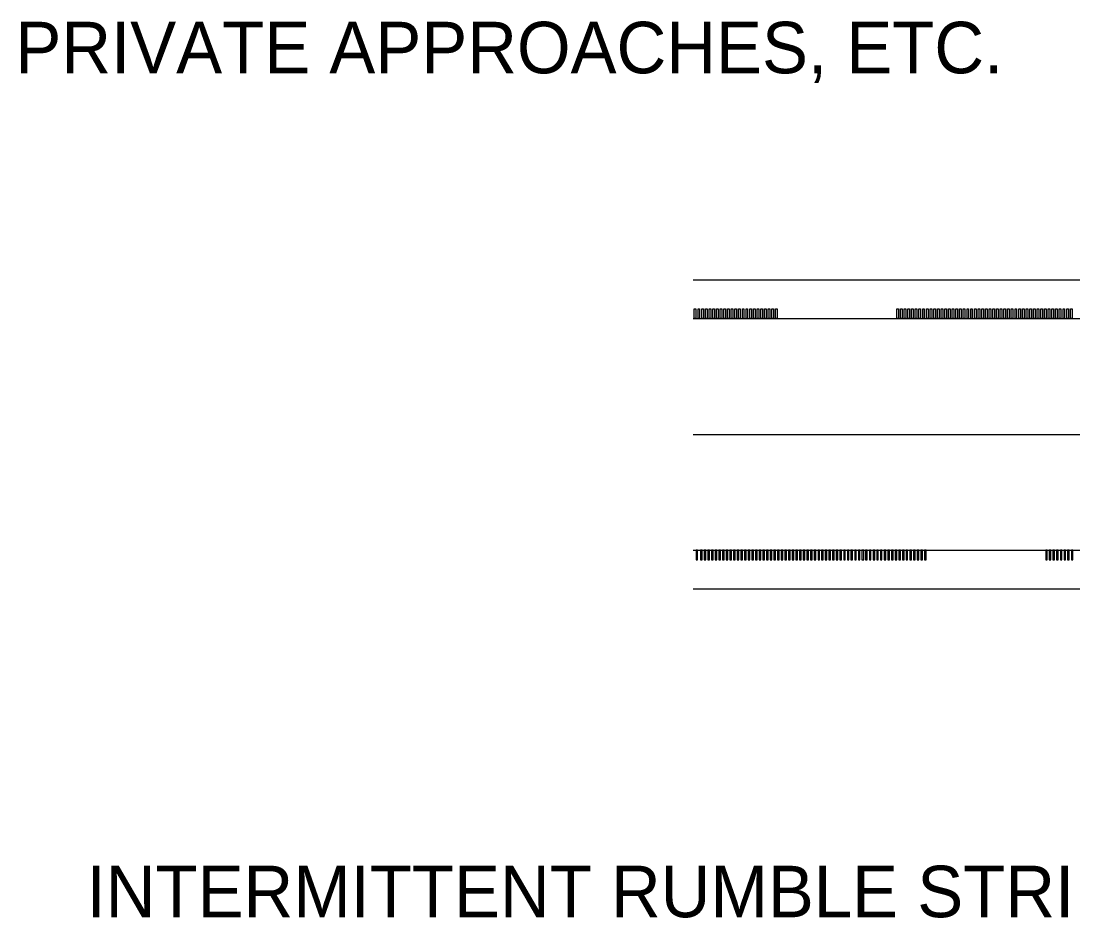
# Model space of a CAD drawing. Extents: x 49991.4 to 50021, y 49987.6 to 50011.4.
# Drawn here: x 50004.547 to 50005.772, y 49993.776 to 49994.821 of the extents above; entities that cross this region are included whole.
import ezdxf

# ---------------------------------------------------------------- set-up
doc = ezdxf.new("R2010")
doc.units = 0
doc.layers.add('Level 1', color=7, linetype='Continuous')
doc.layers.add('Level 2', color=7, linetype='Continuous')

msp = doc.modelspace()

# ---------------------------------------------------------------- linework, layer by layer
at = {"layer": 'Level 1'}
for p, q in [((50005.3297, 49994.5195), (50011.7149, 49994.5195)), ((50005.3297, 49994.4745), (50011.7149, 49994.4745)), ((50005.3297, 49994.3395), (50011.7149, 49994.3395)), ((50005.3299, 49994.2045), (50011.7149, 49994.2045)), ((50005.3299, 49994.1595), (50006.9691, 49994.1595))]:
    msp.add_line(p, q, dxfattribs=at)
for points in [[(50005.3331, 49994.4745), (50005.3312, 49994.4745), (50005.3312, 49994.4857), (50005.3331, 49994.4857)], [(50005.3374, 49994.4745), (50005.3355, 49994.4745), (50005.3355, 49994.4857), (50005.3374, 49994.4857)], [(50005.3417, 49994.4745), (50005.3398, 49994.4745), (50005.3398, 49994.4857), (50005.3417, 49994.4857)], [(50005.346, 49994.4745), (50005.3441, 49994.4745), (50005.3441, 49994.4857), (50005.346, 49994.4857)], [(50005.3503, 49994.4745), (50005.3484, 49994.4745), (50005.3484, 49994.4857), (50005.3503, 49994.4857)], [(50005.3546, 49994.4745), (50005.3527, 49994.4745), (50005.3527, 49994.4857), (50005.3546, 49994.4857)], [(50005.3589, 49994.4745), (50005.357, 49994.4745), (50005.357, 49994.4857), (50005.3589, 49994.4857)], [(50005.3632, 49994.4745), (50005.3613, 49994.4745), (50005.3613, 49994.4857), (50005.3632, 49994.4857)], [(50005.3675, 49994.4745), (50005.3656, 49994.4745), (50005.3656, 49994.4857), (50005.3675, 49994.4857)], [(50005.3718, 49994.4745), (50005.3699, 49994.4745), (50005.3699, 49994.4857), (50005.3718, 49994.4857)], [(50005.3761, 49994.4745), (50005.3742, 49994.4745), (50005.3742, 49994.4857), (50005.3761, 49994.4857)], [(50005.3804, 49994.4745), (50005.3785, 49994.4745), (50005.3785, 49994.4857), (50005.3804, 49994.4857)], [(50005.3847, 49994.4745), (50005.3828, 49994.4745), (50005.3828, 49994.4857), (50005.3847, 49994.4857)], [(50005.389, 49994.4745), (50005.3871, 49994.4745), (50005.3871, 49994.4857), (50005.389, 49994.4857)], [(50005.3933, 49994.4745), (50005.3914, 49994.4745), (50005.3914, 49994.4857), (50005.3933, 49994.4857)], [(50005.3976, 49994.4745), (50005.3957, 49994.4745), (50005.3957, 49994.4857), (50005.3976, 49994.4857)], [(50005.4019, 49994.4745), (50005.4, 49994.4745), (50005.4, 49994.4857), (50005.4019, 49994.4857)], [(50005.4062, 49994.4745), (50005.4043, 49994.4745), (50005.4043, 49994.4857), (50005.4062, 49994.4857)], [(50005.4105, 49994.4745), (50005.4086, 49994.4745), (50005.4086, 49994.4857), (50005.4105, 49994.4857)], [(50005.4148, 49994.4745), (50005.4129, 49994.4745), (50005.4129, 49994.4857), (50005.4148, 49994.4857)], [(50005.4191, 49994.4745), (50005.4172, 49994.4745), (50005.4172, 49994.4857), (50005.4191, 49994.4857)], [(50005.4234, 49994.4745), (50005.4215, 49994.4745), (50005.4215, 49994.4857), (50005.4234, 49994.4857)], [(50005.4277, 49994.4745), (50005.4258, 49994.4745), (50005.4258, 49994.4857), (50005.4277, 49994.4857)], [(50005.5689, 49994.4745), (50005.567, 49994.4745), (50005.567, 49994.4857), (50005.5689, 49994.4857)], [(50005.5732, 49994.4745), (50005.5713, 49994.4745), (50005.5713, 49994.4857), (50005.5732, 49994.4857)], [(50005.5775, 49994.4745), (50005.5756, 49994.4745), (50005.5756, 49994.4857), (50005.5775, 49994.4857)], [(50005.5818, 49994.4745), (50005.5799, 49994.4745), (50005.5799, 49994.4857), (50005.5818, 49994.4857)], [(50005.5861, 49994.4745), (50005.5842, 49994.4745), (50005.5842, 49994.4857), (50005.5861, 49994.4857)], [(50005.5904, 49994.4745), (50005.5885, 49994.4745), (50005.5885, 49994.4857), (50005.5904, 49994.4857)], [(50005.5947, 49994.4745), (50005.5928, 49994.4745), (50005.5928, 49994.4857), (50005.5947, 49994.4857)], [(50005.599, 49994.4745), (50005.5971, 49994.4745), (50005.5971, 49994.4857), (50005.599, 49994.4857)], [(50005.6033, 49994.4745), (50005.6014, 49994.4745), (50005.6014, 49994.4857), (50005.6033, 49994.4857)], [(50005.6076, 49994.4745), (50005.6057, 49994.4745), (50005.6057, 49994.4857), (50005.6076, 49994.4857)], [(50005.6119, 49994.4745), (50005.61, 49994.4745), (50005.61, 49994.4857), (50005.6119, 49994.4857)], [(50005.6162, 49994.4745), (50005.6143, 49994.4745), (50005.6143, 49994.4857), (50005.6162, 49994.4857)], [(50005.6205, 49994.4745), (50005.6186, 49994.4745), (50005.6186, 49994.4857), (50005.6205, 49994.4857)], [(50005.6248, 49994.4745), (50005.6229, 49994.4745), (50005.6229, 49994.4857), (50005.6248, 49994.4857)], [(50005.6291, 49994.4745), (50005.6272, 49994.4745), (50005.6272, 49994.4857), (50005.6291, 49994.4857)], [(50005.6334, 49994.4745), (50005.6315, 49994.4745), (50005.6315, 49994.4857), (50005.6334, 49994.4857)], [(50005.6377, 49994.4745), (50005.6358, 49994.4745), (50005.6358, 49994.4857), (50005.6377, 49994.4857)], [(50005.642, 49994.4745), (50005.6401, 49994.4745), (50005.6401, 49994.4857), (50005.642, 49994.4857)], [(50005.6463, 49994.4745), (50005.6444, 49994.4745), (50005.6444, 49994.4857), (50005.6463, 49994.4857)], [(50005.6506, 49994.4745), (50005.6487, 49994.4745), (50005.6487, 49994.4857), (50005.6506, 49994.4857)], [(50005.6549, 49994.4745), (50005.653, 49994.4745), (50005.653, 49994.4857), (50005.6549, 49994.4857)], [(50005.6592, 49994.4745), (50005.6573, 49994.4745), (50005.6573, 49994.4857), (50005.6592, 49994.4857)], [(50005.6635, 49994.4745), (50005.6616, 49994.4745), (50005.6616, 49994.4857), (50005.6635, 49994.4857)], [(50005.6678, 49994.4745), (50005.6659, 49994.4745), (50005.6659, 49994.4857), (50005.6678, 49994.4857)], [(50005.6721, 49994.4745), (50005.6702, 49994.4745), (50005.6702, 49994.4857), (50005.6721, 49994.4857)], [(50005.6764, 49994.4745), (50005.6745, 49994.4745), (50005.6745, 49994.4857), (50005.6764, 49994.4857)], [(50005.6807, 49994.4745), (50005.6788, 49994.4745), (50005.6788, 49994.4857), (50005.6807, 49994.4857)], [(50005.685, 49994.4745), (50005.6831, 49994.4745), (50005.6831, 49994.4857), (50005.685, 49994.4857)], [(50005.6893, 49994.4745), (50005.6874, 49994.4745), (50005.6874, 49994.4857), (50005.6893, 49994.4857)], [(50005.6936, 49994.4745), (50005.6917, 49994.4745), (50005.6917, 49994.4857), (50005.6936, 49994.4857)], [(50005.6979, 49994.4745), (50005.696, 49994.4745), (50005.696, 49994.4857), (50005.6979, 49994.4857)], [(50005.7022, 49994.4745), (50005.7003, 49994.4745), (50005.7003, 49994.4857), (50005.7022, 49994.4857)], [(50005.7065, 49994.4745), (50005.7046, 49994.4745), (50005.7046, 49994.4857), (50005.7065, 49994.4857)], [(50005.7108, 49994.4745), (50005.7089, 49994.4745), (50005.7089, 49994.4857), (50005.7108, 49994.4857)], [(50005.7151, 49994.4745), (50005.7132, 49994.4745), (50005.7132, 49994.4857), (50005.7151, 49994.4857)], [(50005.7194, 49994.4745), (50005.7175, 49994.4745), (50005.7175, 49994.4857), (50005.7194, 49994.4857)], [(50005.7237, 49994.4745), (50005.7218, 49994.4745), (50005.7218, 49994.4857), (50005.7237, 49994.4857)], [(50005.728, 49994.4745), (50005.7261, 49994.4745), (50005.7261, 49994.4857), (50005.728, 49994.4857)], [(50005.7323, 49994.4745), (50005.7304, 49994.4745), (50005.7304, 49994.4857), (50005.7323, 49994.4857)], [(50005.7366, 49994.4745), (50005.7347, 49994.4745), (50005.7347, 49994.4857), (50005.7366, 49994.4857)], [(50005.7409, 49994.4745), (50005.739, 49994.4745), (50005.739, 49994.4857), (50005.7409, 49994.4857)], [(50005.7452, 49994.4745), (50005.7433, 49994.4745), (50005.7433, 49994.4857), (50005.7452, 49994.4857)], [(50005.7495, 49994.4745), (50005.7476, 49994.4745), (50005.7476, 49994.4857), (50005.7495, 49994.4857)], [(50005.7538, 49994.4745), (50005.7519, 49994.4745), (50005.7519, 49994.4857), (50005.7538, 49994.4857)], [(50005.7581, 49994.4745), (50005.7562, 49994.4745), (50005.7562, 49994.4857), (50005.7581, 49994.4857)], [(50005.7624, 49994.4745), (50005.7605, 49994.4745), (50005.7605, 49994.4857), (50005.7624, 49994.4857)], [(50005.7667, 49994.4745), (50005.7648, 49994.4745), (50005.7648, 49994.4857), (50005.7667, 49994.4857)], [(50005.771, 49994.4745), (50005.7691, 49994.4745), (50005.7691, 49994.4857), (50005.771, 49994.4857)], [(50005.335, 49994.2045), (50005.3332, 49994.2045), (50005.3332, 49994.1933), (50005.335, 49994.1933)], [(50005.3402, 49994.2045), (50005.3384, 49994.2045), (50005.3384, 49994.1933), (50005.3402, 49994.1933)], [(50005.3445, 49994.2045), (50005.3426, 49994.2045), (50005.3426, 49994.1933), (50005.3445, 49994.1933)], [(50005.3488, 49994.2045), (50005.3469, 49994.2045), (50005.3469, 49994.1933), (50005.3488, 49994.1933)], [(50005.3531, 49994.2045), (50005.3512, 49994.2045), (50005.3512, 49994.1933), (50005.3531, 49994.1933)], [(50005.3574, 49994.2045), (50005.3554, 49994.2045), (50005.3554, 49994.1933), (50005.3574, 49994.1933)], [(50005.3616, 49994.2045), (50005.3597, 49994.2045), (50005.3597, 49994.1933), (50005.3616, 49994.1933)], [(50005.3659, 49994.2045), (50005.364, 49994.2045), (50005.364, 49994.1933), (50005.3659, 49994.1933)], [(50005.3702, 49994.2045), (50005.3683, 49994.2045), (50005.3683, 49994.1933), (50005.3702, 49994.1933)], [(50005.3744, 49994.2045), (50005.3726, 49994.2045), (50005.3726, 49994.1933), (50005.3744, 49994.1933)], [(50005.3787, 49994.2045), (50005.3768, 49994.2045), (50005.3768, 49994.1933), (50005.3787, 49994.1933)], [(50005.383, 49994.2045), (50005.3811, 49994.2045), (50005.3811, 49994.1933), (50005.383, 49994.1933)], [(50005.3873, 49994.2045), (50005.3854, 49994.2045), (50005.3854, 49994.1933), (50005.3873, 49994.1933)], [(50005.3916, 49994.2045), (50005.3896, 49994.2045), (50005.3896, 49994.1933), (50005.3916, 49994.1933)], [(50005.3958, 49994.2045), (50005.3939, 49994.2045), (50005.3939, 49994.1933), (50005.3958, 49994.1933)], [(50005.4001, 49994.2045), (50005.3982, 49994.2045), (50005.3982, 49994.1933), (50005.4001, 49994.1933)], [(50005.4044, 49994.2045), (50005.4025, 49994.2045), (50005.4025, 49994.1933), (50005.4044, 49994.1933)], [(50005.4086, 49994.2045), (50005.4068, 49994.2045), (50005.4068, 49994.1933), (50005.4086, 49994.1933)], [(50005.4129, 49994.2045), (50005.411, 49994.2045), (50005.411, 49994.1933), (50005.4129, 49994.1933)], [(50005.4172, 49994.2045), (50005.4153, 49994.2045), (50005.4153, 49994.1933), (50005.4172, 49994.1933)], [(50005.4215, 49994.2045), (50005.4196, 49994.2045), (50005.4196, 49994.1933), (50005.4215, 49994.1933)], [(50005.4258, 49994.2045), (50005.4238, 49994.2045), (50005.4238, 49994.1933), (50005.4258, 49994.1933)], [(50005.43, 49994.2045), (50005.4281, 49994.2045), (50005.4281, 49994.1933), (50005.43, 49994.1933)], [(50005.4343, 49994.2045), (50005.4324, 49994.2045), (50005.4324, 49994.1933), (50005.4343, 49994.1933)], [(50005.4386, 49994.2045), (50005.4367, 49994.2045), (50005.4367, 49994.1933), (50005.4386, 49994.1933)], [(50005.4428, 49994.2045), (50005.441, 49994.2045), (50005.441, 49994.1933), (50005.4428, 49994.1933)], [(50005.4471, 49994.2045), (50005.4452, 49994.2045), (50005.4452, 49994.1933), (50005.4471, 49994.1933)], [(50005.4514, 49994.2045), (50005.4495, 49994.2045), (50005.4495, 49994.1933), (50005.4514, 49994.1933)], [(50005.4557, 49994.2045), (50005.4538, 49994.2045), (50005.4538, 49994.1933), (50005.4557, 49994.1933)], [(50005.46, 49994.2045), (50005.458, 49994.2045), (50005.458, 49994.1933), (50005.46, 49994.1933)], [(50005.4642, 49994.2045), (50005.4623, 49994.2045), (50005.4623, 49994.1933), (50005.4642, 49994.1933)], [(50005.4685, 49994.2045), (50005.4666, 49994.2045), (50005.4666, 49994.1933), (50005.4685, 49994.1933)], [(50005.4728, 49994.2045), (50005.4709, 49994.2045), (50005.4709, 49994.1933), (50005.4728, 49994.1933)], [(50005.477, 49994.2045), (50005.4752, 49994.2045), (50005.4752, 49994.1933), (50005.477, 49994.1933)], [(50005.4813, 49994.2045), (50005.4794, 49994.2045), (50005.4794, 49994.1933), (50005.4813, 49994.1933)], [(50005.4856, 49994.2045), (50005.4837, 49994.2045), (50005.4837, 49994.1933), (50005.4856, 49994.1933)], [(50005.4899, 49994.2045), (50005.488, 49994.2045), (50005.488, 49994.1933), (50005.4899, 49994.1933)], [(50005.4942, 49994.2045), (50005.4922, 49994.2045), (50005.4922, 49994.1933), (50005.4942, 49994.1933)], [(50005.4984, 49994.2045), (50005.4965, 49994.2045), (50005.4965, 49994.1933), (50005.4984, 49994.1933)], [(50005.5027, 49994.2045), (50005.5008, 49994.2045), (50005.5008, 49994.1933), (50005.5027, 49994.1933)], [(50005.507, 49994.2045), (50005.5051, 49994.2045), (50005.5051, 49994.1933), (50005.507, 49994.1933)], [(50005.5112, 49994.2045), (50005.5094, 49994.2045), (50005.5094, 49994.1933), (50005.5112, 49994.1933)], [(50005.5155, 49994.2045), (50005.5136, 49994.2045), (50005.5136, 49994.1933), (50005.5155, 49994.1933)], [(50005.5198, 49994.2045), (50005.5179, 49994.2045), (50005.5179, 49994.1933), (50005.5198, 49994.1933)], [(50005.5241, 49994.2045), (50005.5222, 49994.2045), (50005.5222, 49994.1933), (50005.5241, 49994.1933)], [(50005.5284, 49994.2045), (50005.5264, 49994.2045), (50005.5264, 49994.1933), (50005.5284, 49994.1933)], [(50005.5326, 49994.2045), (50005.5307, 49994.2045), (50005.5307, 49994.1933), (50005.5326, 49994.1933)], [(50005.5369, 49994.2045), (50005.535, 49994.2045), (50005.535, 49994.1933), (50005.5369, 49994.1933)], [(50005.5412, 49994.2045), (50005.5393, 49994.2045), (50005.5393, 49994.1933), (50005.5412, 49994.1933)], [(50005.5454, 49994.2045), (50005.5436, 49994.2045), (50005.5436, 49994.1933), (50005.5454, 49994.1933)], [(50005.5497, 49994.2045), (50005.5478, 49994.2045), (50005.5478, 49994.1933), (50005.5497, 49994.1933)], [(50005.554, 49994.2045), (50005.5521, 49994.2045), (50005.5521, 49994.1933), (50005.554, 49994.1933)], [(50005.5583, 49994.2045), (50005.5564, 49994.2045), (50005.5564, 49994.1933), (50005.5583, 49994.1933)], [(50005.5626, 49994.2045), (50005.5606, 49994.2045), (50005.5606, 49994.1933), (50005.5626, 49994.1933)], [(50005.5668, 49994.2045), (50005.5649, 49994.2045), (50005.5649, 49994.1933), (50005.5668, 49994.1933)], [(50005.5711, 49994.2045), (50005.5692, 49994.2045), (50005.5692, 49994.1933), (50005.5711, 49994.1933)], [(50005.5754, 49994.2045), (50005.5735, 49994.2045), (50005.5735, 49994.1933), (50005.5754, 49994.1933)], [(50005.5796, 49994.2045), (50005.5778, 49994.2045), (50005.5778, 49994.1933), (50005.5796, 49994.1933)], [(50005.5839, 49994.2045), (50005.582, 49994.2045), (50005.582, 49994.1933), (50005.5839, 49994.1933)], [(50005.5882, 49994.2045), (50005.5863, 49994.2045), (50005.5863, 49994.1933), (50005.5882, 49994.1933)], [(50005.5925, 49994.2045), (50005.5906, 49994.2045), (50005.5906, 49994.1933), (50005.5925, 49994.1933)], [(50005.5968, 49994.2045), (50005.5948, 49994.2045), (50005.5948, 49994.1933), (50005.5968, 49994.1933)], [(50005.601, 49994.2045), (50005.5991, 49994.2045), (50005.5991, 49994.1933), (50005.601, 49994.1933)], [(50005.7422, 49994.2045), (50005.7403, 49994.2045), (50005.7403, 49994.1933), (50005.7422, 49994.1933)], [(50005.7465, 49994.2045), (50005.7445, 49994.2045), (50005.7445, 49994.1933), (50005.7465, 49994.1933)], [(50005.7507, 49994.2045), (50005.7488, 49994.2045), (50005.7488, 49994.1933), (50005.7507, 49994.1933)], [(50005.755, 49994.2045), (50005.7531, 49994.2045), (50005.7531, 49994.1933), (50005.755, 49994.1933)], [(50005.7593, 49994.2045), (50005.7574, 49994.2045), (50005.7574, 49994.1933), (50005.7593, 49994.1933)], [(50005.7635, 49994.2045), (50005.7617, 49994.2045), (50005.7617, 49994.1933), (50005.7635, 49994.1933)], [(50005.7678, 49994.2045), (50005.7659, 49994.2045), (50005.7659, 49994.1933), (50005.7678, 49994.1933)], [(50005.7721, 49994.2045), (50005.7702, 49994.2045), (50005.7702, 49994.1933), (50005.7721, 49994.1933)]]:
    msp.add_lwpolyline(points, close=True, dxfattribs=at)

# ---------------------------------------------------------------- texts
at = {"layer": 'Level 2'}
msp.add_text('PRIVATE APPROACHES, ETC.', height=0.06, dxfattribs=at).set_placement((50004.5406, 49994.7601))
msp.add_text('INTERMITTENT RUMBLE STRIPS', height=0.06, rotation=359.9999, dxfattribs=at).set_placement((50004.6235, 49993.777))

doc.saveas('drawing.dxf')
